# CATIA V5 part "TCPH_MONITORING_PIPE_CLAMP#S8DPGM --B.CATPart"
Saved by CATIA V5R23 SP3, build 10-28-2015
Part number: TCPH_MONITORING_PIPE_CLAMP#S8DPF4
Revision: --B
Nomenclature: _
Description: TCPH_MONITORING_PIPE_CLAMP
Property "ID": "S8DPF4"
Property "AT": "PD"
Property "REP": "CM"
Property "External Part ID": "_"
Property "PREF": "Y"
Property "LONG": "_"
Property "PBS 1": "24"
Property "PBS 2": "CR"
Property "PBS 3": "LC"
Property "DEPT": "_"
Property "DIVN": "_"
Property "GROUP": "_"
Property "UNIT": "_"
Property "PARTY": "_"
Property "RO": "IOKIK"
Property "RE": "VITUPIG"
Property "PRO": "---"
Property "Change Type": "Major"
Property "Maturity Level": "CD"
Property "Export Number": "_"
Property "Description Modification": "FDRModel"
Property "Description Documents": "_"
Property "BOM": "_"
Property "User In Enovia": "BLANCHA"
Property "Object Type": "_"
Property "CADENAS_ID": "_"
Property "Life Cycle Status": "Approved"
Material "X2CrNi18-09 1.4307 (304L)": density 8000 kg/m3, Young's modulus 1.93e+11 Pa, Poisson ratio 0.3, thermal expansion 1.6e-05 1/K
Bounding box of the stored display mesh (mm): x 13100 to 13174, y 860 to 890, z -4424.5 to -4361.5
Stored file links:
  C:\Users\pandeym\Desktop\__TCPH\TCPH_MONITORING_PIPE_CLAMP#S8DPGM --B.CATPart
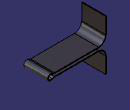
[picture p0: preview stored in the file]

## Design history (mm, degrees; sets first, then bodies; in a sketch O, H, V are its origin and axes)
Set1
  Sketch1 "TCPH_MONITORING_PIPE_CLAMP", origin (13170, 875, -4393), H (1, 0, 0), V (0, 0, 1), geometry linked from another document
Body1 (main body)
  Pad1: profile Sketch1, direction (0, -1, 0), length 15, mirrored extent, thin wall 0, second thickness 1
